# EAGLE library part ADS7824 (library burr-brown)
4-Channel, 12-Bit Sampling CMOS ADC
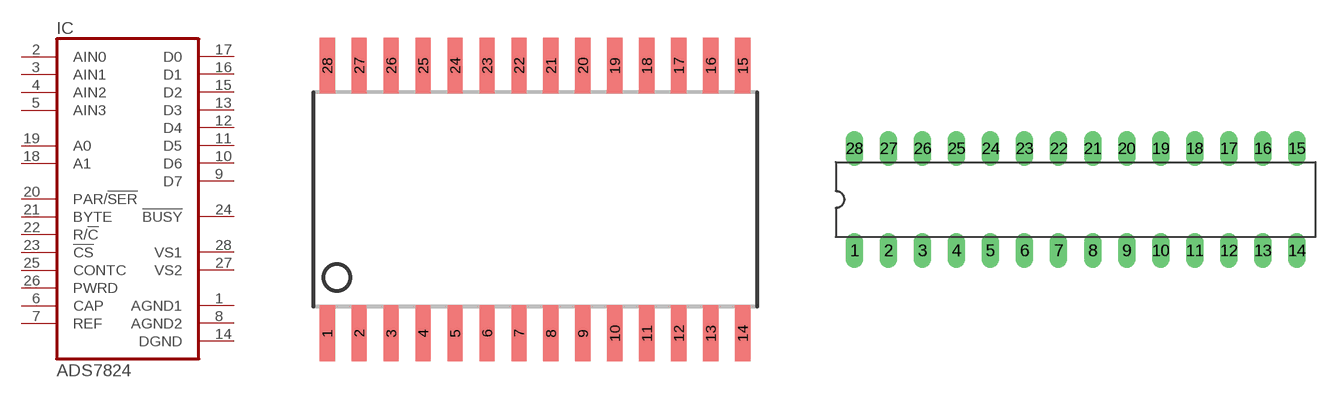
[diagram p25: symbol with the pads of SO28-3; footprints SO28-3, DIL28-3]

Designator prefix IC

## ADS7824U (MF: TEXAS INSTRUMENTS; MPN: ADS7824U; OC_FARNELL: 1106198; OC_NEWARK: 35C1550)  [SO28-3]
1  AGND1  pwr
2  AIN0  in
3  AIN1  in
4  AIN2  in
5  AIN3  in
6  CAP  in
7  REF
8  AGND2  pwr
9  D7  out
10  D6  out
11  D5  out
12  D4
13  D3  out
14  DGND  pwr
15  D2
16  D1  out
17  D0
18  A1
19  A0
20  PAR/!SER  in
21  BYTE  in
22  R/!C  in
23  !CS  in
24  !BUSY  out
25  CONTC  in
26  PWRD  in
27  VS2  pwr
28  VS1  pwr

## ADS7824P (MF: TEXAS INSTRUMENT CONNECTORS; MPN: ADS7824P; OC_FARNELL: 1648604; OC_NEWARK: 14M8149)  [DIL28-3]
Pads as for SO28-3

## Footprint SO28-3 (pad centres in mm)
Small Outline Package
smd 0.61 x 2.21: 1 -8.255,-5.315; 2 -6.985,-5.315; 3 -5.715,-5.315; 4 -4.445,-5.315; 5 -3.175,-5.315; 6 -1.905,-5.315; 7 -0.635,-5.315; 8 0.635,-5.315; 9 1.905,-5.315; 10 3.175,-5.315; 11 4.445,-5.315; 12 5.715,-5.315; 13 6.985,-5.315; 14 8.255,-5.315; 15 8.255,5.315; 16 6.985,5.315; 17 5.715,5.315; 18 4.445,5.315; 19 3.175,5.315; 20 1.905,5.315; 21 0.635,5.315; 22 -0.635,5.315; 23 -1.905,5.315; 24 -3.175,5.315; 25 -4.445,5.315; 26 -5.715,5.315; 27 -6.985,5.315; 28 -8.255,5.315

## Footprint DIL28-3 (pad centres in mm)
Dual In Line 0.3 inch
drill 0.813 long: 1 -16.51,-3.81; 2 -13.97,-3.81; 3 -11.43,-3.81; 4 -8.89,-3.81; 5 -6.35,-3.81; 6 -3.81,-3.81; 7 -1.27,-3.81; 8 1.27,-3.81; 9 3.81,-3.81; 10 6.35,-3.81; 11 8.89,-3.81; 12 11.43,-3.81; 13 13.97,-3.81; 14 16.51,-3.81; 15 16.51,3.81; 16 13.97,3.81; 17 11.43,3.81; 18 8.89,3.81; 19 6.35,3.81; 20 3.81,3.81; 21 1.27,3.81; 22 -1.27,3.81; 23 -3.81,3.81; 24 -6.35,3.81; 25 -8.89,3.81; 26 -11.43,3.81; 27 -13.97,3.81; 28 -16.51,3.81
